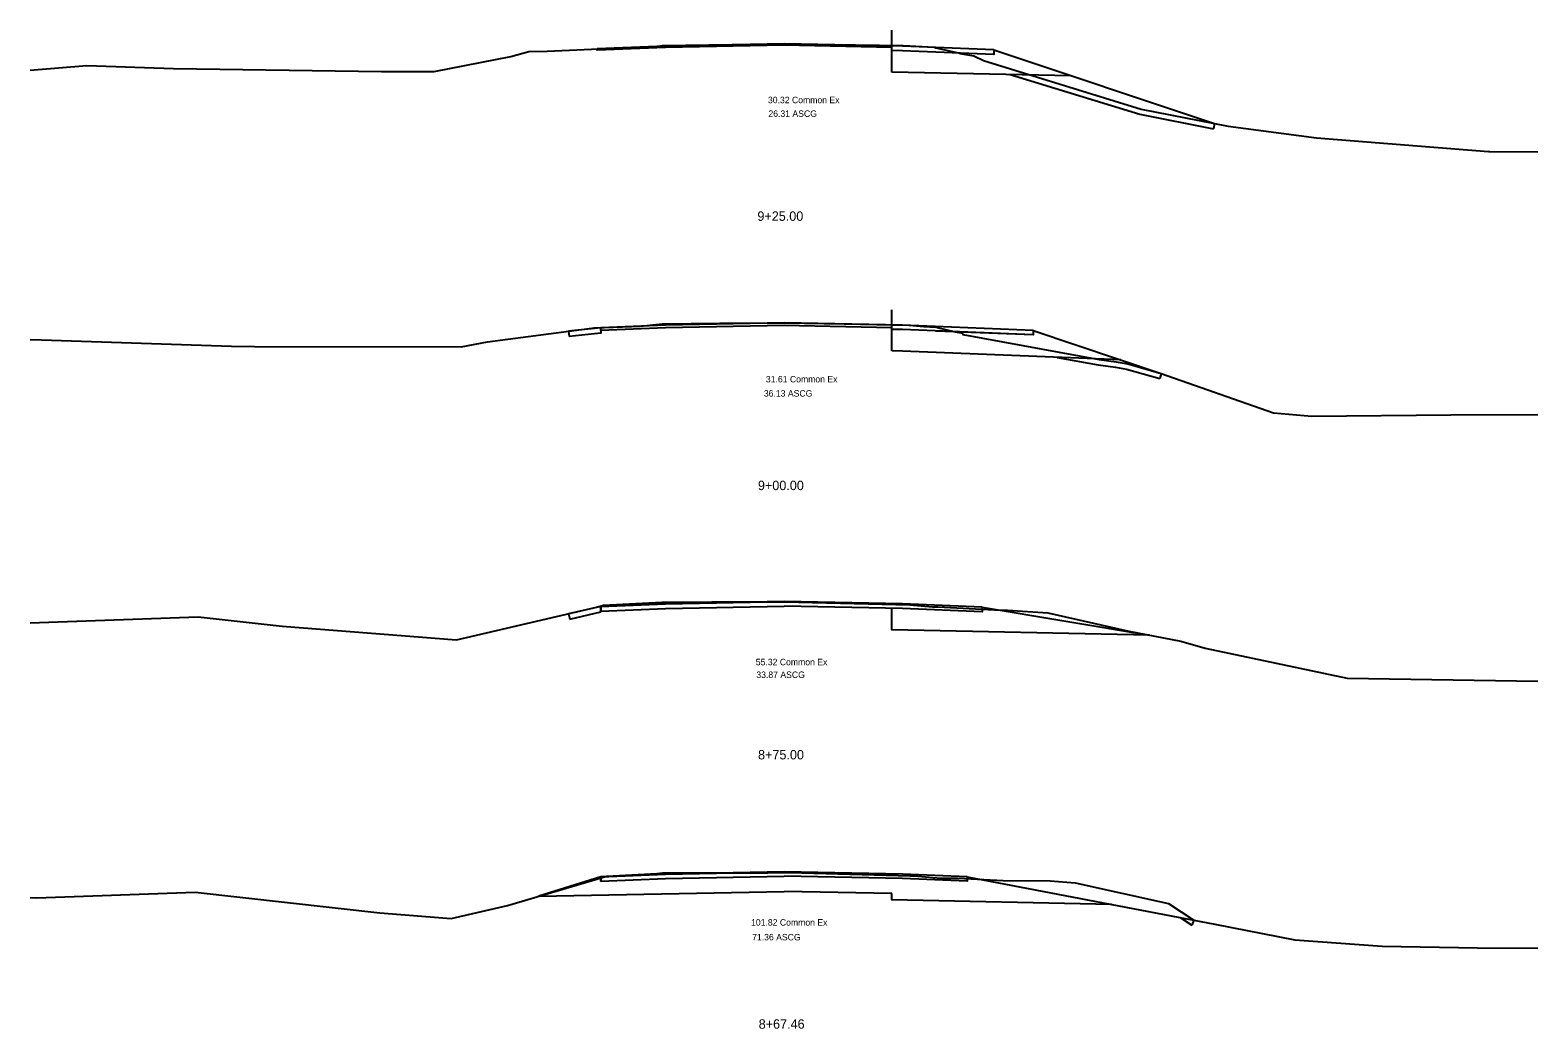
# Model space of a CAD drawing. Extents: x 2194502 to 2194968, y 863888 to 863998.
# Drawn here: x 2194828.5 to 2194968.5, y 863893.6 to 863986.3 of the extents above; entities that cross this region are included whole.
import ezdxf

# ---------------------------------------------------------------- set-up
doc = ezdxf.new("R2010")
doc.units = 0
for name, color, linetype in [('Approach', 7, 'Continuous'), ('H_V ANNOTATION', 7, 'Continuous'), ('Junk', 7, 'Continuous'), ('S_Roadway_Centerline', 7, 'Continuous'), ('TEMPLATE', 7, 'Continuous')]:
    doc.layers.add(name, color=color, linetype=linetype)

msp = doc.modelspace()

# ---------------------------------------------------------------- linework, layer by layer
at = {"layer": 'Junk'}
for p, q in [((2194908.5, 863983.52), (2194908.5, 863986.27)), ((2194908.5, 863957.57), (2194908.5, 863960.32))]:
    msp.add_line(p, q, dxfattribs=at)
at = {"layer": 'S_Roadway_Centerline'}
for points in [[(2194828.5, 863982.56), (2194833.75, 863982.98), (2194841.81, 863982.71), (2194861.13, 863982.44), (2194866, 863982.43), (2194873.12, 863983.82), (2194874.81, 863984.28), (2194876.5, 863984.31), (2194883.39, 863984.63), (2194886.92, 863984.8), (2194887.22, 863984.84), (2194897.98, 863984.99), (2194898.5, 863984.99), (2194909.58, 863984.84), (2194910.08, 863984.82), (2194910.19, 863984.82), (2194912.44, 863984.68), (2194912.6, 863984.64), (2194914.83, 863984.12), (2194914.84, 863984.11), (2194916.13, 863983.88), (2194917.01, 863983.44), (2194931.66, 863978.95), (2194939.75, 863977.35), (2194947.96, 863976.29), (2194963.93, 863975.02), (2194964.03, 863975.02), (2194968.5, 863974.98)], [(2194828.5, 863957.55), (2194829.55, 863957.51), (2194847.19, 863956.93), (2194849.32, 863956.9), (2194868.53, 863956.87), (2194870.98, 863957.34), (2194880.42, 863958.57), (2194880.88, 863958.64), (2194880.95, 863958.64), (2194885.16, 863958.79), (2194887.19, 863959.01), (2194892.54, 863959.08), (2194898.5, 863959.1), (2194904.09, 863959.02), (2194910.13, 863958.87), (2194911.48, 863958.77), (2194912.6, 863958.7), (2194914.4, 863958.28), (2194915.07, 863958.13), (2194915.09, 863958.01), (2194927.75, 863955.69), (2194929.34, 863955.49), (2194930.42, 863955.28), (2194933.53, 863954.4), (2194943.95, 863950.76), (2194947.52, 863950.45), (2194960.42, 863950.56), (2194968.5, 863950.6)], [(2194828.5, 863931.25), (2194844.1, 863931.81), (2194851.91, 863930.95), (2194868.08, 863929.67), (2194881.1, 863932.69), (2194881.74, 863932.88), (2194887.14, 863933.18), (2194887.16, 863933.18), (2194891.81, 863933.19), (2194898.5, 863933.21), (2194898.59, 863933.21), (2194910.18, 863932.91), (2194912.28, 863932.75), (2194912.76, 863932.72), (2194912.77, 863932.72), (2194918.05, 863932.45), (2194919.25, 863932.44), (2194922.99, 863932.17), (2194930.53, 863930.49), (2194935.35, 863929.56), (2194937.62, 863928.91), (2194950.8, 863926.1), (2194968.5, 863925.83)], [(2194828.5, 863905.76), (2194829.11, 863905.73), (2194843.83, 863906.25), (2194860.97, 863904.34), (2194867.6, 863903.81), (2194872.82, 863905.01), (2194882.06, 863907.73), (2194886.68, 863907.98), (2194887.21, 863908.03), (2194896.99, 863908.05), (2194898.48, 863908.07), (2194900.17, 863908.03), (2194910.22, 863907.77), (2194910.93, 863907.72), (2194913.06, 863907.56), (2194914.67, 863907.54), (2194918.84, 863907.33), (2194923.2, 863907.29), (2194925.54, 863907.12), (2194934.21, 863905.19), (2194936.56, 863903.65), (2194938.49, 863903.28), (2194945.92, 863901.82), (2194954.03, 863901.23), (2194962.9, 863901.07), (2194968.5, 863901.04)]]:
    msp.add_lwpolyline(points, dxfattribs=at)
at = {"layer": 'TEMPLATE'}
for p, q in [((2194887.5, 863984.77), (2194898.5, 863984.99)), ((2194898.5, 863984.99), (2194887.5, 863984.77)), ((2194898.5, 863984.87), (2194887.5, 863984.65)), ((2194909.5, 863984.77), (2194898.5, 863984.99)), ((2194908.5, 863984.67), (2194898.5, 863984.87)), ((2194887.5, 863984.77), (2194881.15, 863984.53)), ((2194908.5, 863982.37), (2194908.5, 863984.67)), ((2194909.5, 863984.35), (2194908.5, 863984.37)), ((2194917.99, 863984.43), (2194909.5, 863984.77)), ((2194925.16, 863982.04), (2194908.5, 863982.37)), ((2194938.48, 863977.6), (2194938.38, 863977.11)), ((2194881.5, 863958.64), (2194878.5, 863958.32)), ((2194878.5, 863958.32), (2194878.55, 863957.83)), ((2194887.5, 863958.88), (2194881.5, 863958.64)), ((2194898.5, 863959.1), (2194887.5, 863958.88)), ((2194898.5, 863958.85), (2194887.5, 863958.63)), ((2194909.5, 863958.88), (2194898.5, 863959.1)), ((2194908.5, 863958.65), (2194898.5, 863958.85)), ((2194909.5, 863958.47), (2194908.5, 863958.49)), ((2194921.63, 863958.4), (2194909.5, 863958.88)), ((2194921.63, 863957.98), (2194909.5, 863958.47)), ((2194921.63, 863958.4), (2194933.53, 863954.4)), ((2194909.5, 863956.47), (2194908.5, 863956.49)), ((2194929.79, 863955.65), (2194909.5, 863956.47)), ((2194933.53, 863954.4), (2194933.4, 863953.92)), ((2194887.5, 863933), (2194898.5, 863933.22)), ((2194898.5, 863933.22), (2194887.5, 863933)), ((2194909.5, 863933), (2194898.5, 863933.22)), ((2194881.5, 863932.76), (2194878.5, 863932.09)), ((2194878.5, 863932.09), (2194878.61, 863931.6)), ((2194887.5, 863933), (2194881.5, 863932.76)), ((2194887.5, 863932.58), (2194898.5, 863932.8)), ((2194909.5, 863932.58), (2194898.5, 863932.8)), ((2194916.89, 863932.7), (2194909.5, 863933)), ((2194916.89, 863932.7), (2194932.44, 863930.12)), ((2194887.5, 863907.92), (2194881.5, 863907.68)), ((2194887.5, 863907.92), (2194898.5, 863908.14)), ((2194898.5, 863908.14), (2194887.5, 863907.92)), ((2194909.5, 863907.92), (2194898.5, 863908.14)), ((2194915.5, 863907.68), (2194909.5, 863907.92)), ((2194881.5, 863907.68), (2194875.73, 863905.87)), ((2194887.5, 863907.5), (2194898.5, 863907.72)), ((2194909.5, 863907.5), (2194898.5, 863907.72)), ((2194915.5, 863907.68), (2194936.56, 863903.65)), ((2194875.73, 863905.87), (2194898.5, 863906.32)), ((2194908.5, 863906.12), (2194898.5, 863906.32)), ((2194936.56, 863903.65), (2194936.37, 863903.18))]:
    msp.add_line(p, q, dxfattribs=at)
for points in [[(2194887.5, 863984.65), (2194881.15, 863984.4), (2194881.15, 863984.53)], [(2194917.99, 863984.43), (2194917.99, 863984.02), (2194909.5, 863984.35)], [(2194917.99, 863984.43), (2194938.48, 863977.6)], [(2194919.51, 863982.15), (2194931.53, 863978.47), (2194938.38, 863977.11)], [(2194881.5, 863958.39), (2194881.5, 863958.14), (2194878.55, 863957.83)], [(2194887.5, 863958.63), (2194881.5, 863958.39), (2194881.5, 863958.64)], [(2194908.5, 863956.49), (2194908.5, 863958.65)], [(2194921.63, 863958.4), (2194921.63, 863957.98), (2194912.6, 863958.34)], [(2194923.85, 863955.89), (2194927.67, 863955.19), (2194929.27, 863955), (2194930.3, 863954.8), (2194933.4, 863953.92)], [(2194878.61, 863931.6), (2194881.5, 863932.27), (2194881.5, 863932.34)], [(2194881.5, 863932.76), (2194881.5, 863932.76), (2194887.5, 863933)], [(2194881.5, 863932.34), (2194881.5, 863932.76), (2194881.5, 863932.34), (2194887.5, 863932.58)], [(2194932.44, 863930.12), (2194908.5, 863930.6), (2194908.5, 863932.6)], [(2194916.89, 863932.7), (2194916.89, 863932.28), (2194909.5, 863932.58)], [(2194881.5, 863907.68), (2194881.5, 863907.68), (2194887.5, 863907.92)], [(2194881.5, 863907.26), (2194881.5, 863907.68), (2194881.5, 863907.26), (2194887.5, 863907.5)], [(2194915.5, 863907.68), (2194915.5, 863907.26), (2194909.5, 863907.5)], [(2194928.9, 863905.11), (2194908.5, 863905.52), (2194908.5, 863906.12)], [(2194935.28, 863903.89), (2194936.37, 863903.18)]]:
    msp.add_lwpolyline(points, dxfattribs=at)

# ---------------------------------------------------------------- texts
at = {"layer": 'Approach'}
for s, p in [('30.32 Common Ex', (2194897.01, 863979.49)), ('26.31 ASCG', (2194897.05, 863978.22)), ('31.61 Common Ex', (2194896.82, 863953.57)), ('36.13 ASCG', (2194896.63, 863952.25)), ('55.32 Common Ex', (2194895.88, 863927.31)), ('33.87 ASCG', (2194895.93, 863926.13)), ('101.82 Common Ex', (2194895.44, 863903.14)), ('71.36 ASCG', (2194895.54, 863901.77))]:
    msp.add_text(s, height=0.6, dxfattribs=at).set_placement(p)
at = {"layer": 'H_V ANNOTATION'}
for s, p in [('9+25.00', (2194896.03, 863968.57)), ('9+00.00', (2194896.08, 863943.57)), ('8+75.00', (2194896.09, 863918.57)), ('8+67.46', (2194896.15, 863893.57))]:
    msp.add_text(s, height=0.875, dxfattribs=at).set_placement(p)

doc.saveas('drawing.dxf')
